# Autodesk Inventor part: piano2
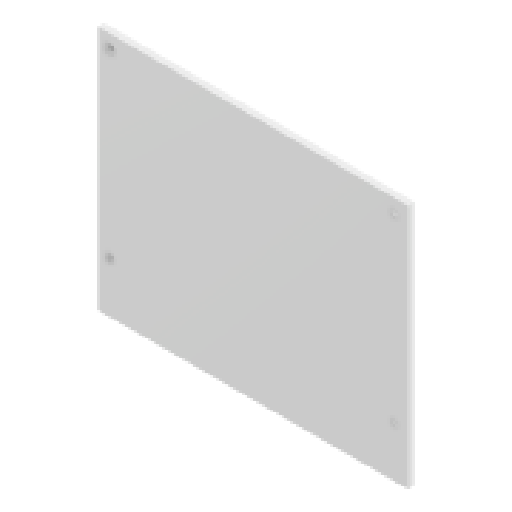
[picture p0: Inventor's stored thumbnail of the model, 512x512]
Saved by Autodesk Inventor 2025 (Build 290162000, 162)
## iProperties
Created: 2025-05
Part Number: piano2
Material: Plastica ABS
Document SubType Name: Modeling
Designer: R5800u
Density: 1.06 g/cm^3
Appearance: Liscia - Bianco
Author: R5800u
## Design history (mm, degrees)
sketch "Schizzo1"
  geometry: L1 (-9, 10)-(-3.3, 10) reference; L2 (-10, 3.3)-(-10, 9) reference; L3 (-10, 10)-(230, 10); L4 (230, 10)-(230, -180); L5 (230, -180)-(-10, -180); L6 (-10, -180)-(-10, 10); C1 r 2.5 at (0, 0); C2 r 2.5 at (220, 0); C3 r 2.1 at (0, -140) reference; C4 r 2.1 at (220, -140) reference; C5 r 2.1 at (220, 0) reference; C6 r 3.235 at (0, 0) reference; 5 further points
  constraints: 8 end point, 2 centre point, 2 coincident, 2 parallel, 1 horizontal, 1 perpendicular
  dimensions: "d0" = 240 distance of L4.end L5.end; "d1" = 190 distance of L3.end L4.end; "d2" = 5 diameter of C1; "d3" = 5 diameter of C2
extrude "Estrusione1" new body sketch "Schizzo1" distance "d4" = 5; taper "d5" = 0 deg; dims "d2" = 5
node "Solido1"
node "Riferimento1"
node "Riferimento2"
node "Riferimento3"
node "Riferimento4"
node "Riferimento5"
node "Riferimento6"
